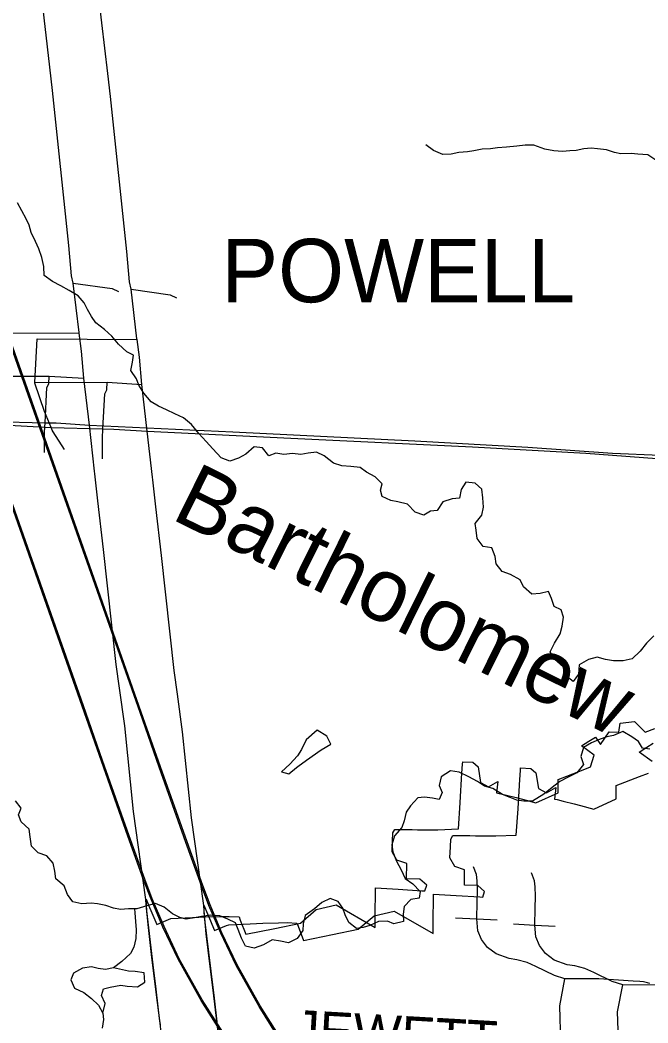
# Model space of a CAD drawing. Extents: x -38.2 to 41.9, y -4 to 24.9.
# Drawn here: x 7.082 to 8.019, y 16.76 to 18.257 of the extents above; entities that cross this region are included whole.
import ezdxf

# ---------------------------------------------------------------- set-up
doc = ezdxf.new("R2010")
doc.units = 0
for name, color, linetype in [('Default', 7, 'Continuous'), ('GM_X_City_Street', 7, 'Continuous'), ('GM_X_Corporation_Text', 7, 'Continuous'), ('GM_X_County_Road', 7, 'Continuous'), ('GM_X_Interchange_Ramps', 7, 'Continuous'), ('GM_X_Interstate_Location', 7, 'Continuous'), ('GM_X_Minor_Lake', 7, 'Continuous'), ('GM_X_Minor_River', 7, 'Continuous'), ('GM_X_Minor_River_Text', 7, 'Continuous'), ('GM_X_Rail_Line', 7, 'Continuous'), ('GM_X_Rail_Line_Text', 7, 'Continuous'), ('GM_X_State_Location', 7, 'Continuous'), ('GM_X_State_Route', 7, 'Continuous'), ('GM_X_Township_Road', 7, 'Continuous'), ('GM_X_Township_Road_Text', 7, 'Continuous')]:
    doc.layers.add(name, color=color, linetype=linetype)

msp = doc.modelspace()

# ---------------------------------------------------------------- linework, layer by layer
at = {"layer": 'Default'}
msp.add_lwpolyline([(7.2912, 16.7571), (7.2901, 16.7666), (7.2848, 16.8105), (7.2805, 16.8466), (7.2707, 16.9276), (7.2698, 16.9449), (7.2698, 16.945), (7.275, 16.9323), (7.2768, 16.9278), (7.2842, 16.9107), (7.2857, 16.9072), (7.3032, 16.9145), (7.3068, 16.9159), (7.3389, 16.9172), (7.3578, 16.9183), (7.3812, 16.9188), (7.3939, 16.9191), (7.4086, 16.9183), (7.4104, 16.9136), (7.4186, 16.8924), (7.4618, 16.9012), (7.5001, 16.9089), (7.5237, 16.9292), (7.5386, 16.9327), (7.5537, 16.9363), (7.6119, 16.9026), (7.612, 16.9141), (7.612, 16.9167), (7.6124, 16.9615), (7.6461, 16.9595), (7.6817, 16.9575), (7.6861, 16.9572), (7.6887, 16.9656), (7.6787, 16.9746), (7.6588, 16.975), (7.6589, 16.9979), (7.644, 17.0028), (7.637, 17.0154), (7.6378, 17.032), (7.6384, 17.0438), (7.6412, 17.0489), (7.6668, 17.049), (7.6752, 17.0485), (7.7056, 17.0485), (7.7361, 17.0497), (7.7387, 17.0887), (7.7387, 17.0892), (7.7414, 17.1328), (7.7423, 17.1462), (7.7425, 17.15), (7.7576, 17.1491), (7.7655, 17.1423), (7.7689, 17.1191), (7.7811, 17.1126), (7.7951, 17.1207), (7.7931, 17.1035), (7.7968, 17.1026), (7.8059, 17.1005), (7.8222, 17.0965), (7.8317, 17.0939), (7.8517, 17.0884), (7.8851, 17.1037), (7.885, 17.1236), (7.9198, 17.1371), (7.9333, 17.1423), (7.9387, 17.1597), (7.9197, 17.1736), (7.9309, 17.1807), (7.9405, 17.1869), (7.9482, 17.1757), (7.9612, 17.1945), (7.9758, 17.1942), (7.9776, 17.2075), (7.9987, 17.2102), (8.0059, 17.203), (8.0151, 17.194), (8.0295, 17.1998)], dxfattribs=at)
at = {"layer": 'GM_X_City_Street'}
msp.add_line((7.021, 17.7906), (7.1699, 17.7898), dxfattribs=at)
for points in [[(7.161, 17.8646), (7.2193, 17.8564), (7.2288, 17.8519)], [(7.0172, 17.7254), (7.125, 17.7257), (7.1769, 17.7225)], [(7.1183, 17.6425), (7.119, 17.6561), (7.1217, 17.7086), (7.1247, 17.7143), (7.125, 17.7257)], [(7.1182, 17.6115), (7.1182, 17.6415), (7.1183, 17.6425)]]:
    msp.add_lwpolyline(points, dxfattribs=at)
at = {"layer": 'GM_X_County_Road'}
for p, q in [((7.1262, 18.1868), (7.1021, 18.3947)), ((7.1928, 17.5839), (7.1852, 17.6526))]:
    msp.add_line(p, q, dxfattribs=at)
for points in [[(7.1698, 17.7908), (7.161, 17.8646), (7.1585, 17.8754), (7.1547, 17.9208), (7.1302, 18.1522), (7.1262, 18.1868)], [(7.1852, 17.6526), (7.1769, 17.7225), (7.1735, 17.763), (7.1699, 17.7898), (7.1698, 17.7908)], [(7.2302, 17.2599), (7.2254, 17.2953), (7.2063, 17.4669), (7.1978, 17.5395), (7.1933, 17.58), (7.1928, 17.5839)], [(7.27, 16.9364), (7.2693, 16.9444), (7.251, 17.0755), (7.2379, 17.2037), (7.2302, 17.2599)], [(8.0252, 17.1505), (8.0061, 17.1644), (8.0173, 17.1715), (8.027, 17.1777)], [(7.3766, 16.7574), (7.3713, 16.8013), (7.367, 16.8374), (7.3572, 16.9185), (7.3562, 16.9358), (7.3562, 16.9358), (7.3614, 16.9231), (7.3633, 16.9186), (7.3706, 16.9015), (7.3722, 16.898), (7.3897, 16.9053), (7.3933, 16.9067), (7.4254, 16.908), (7.4443, 16.9091), (7.4676, 16.9096), (7.4804, 16.9099), (7.4951, 16.9091), (7.4969, 16.9044), (7.505, 16.8832), (7.5482, 16.892), (7.5866, 16.8998), (7.6102, 16.92), (7.6251, 16.9236), (7.6402, 16.9271), (7.6984, 16.8934), (7.6985, 16.9049), (7.6985, 16.9075), (7.6989, 16.9523), (7.7326, 16.9503), (7.7682, 16.9483), (7.7726, 16.948), (7.7751, 16.9564), (7.7652, 16.9654), (7.7453, 16.9658), (7.7454, 16.9887), (7.7305, 16.9936), (7.7235, 17.0063), (7.7243, 17.0228), (7.7249, 17.0346), (7.7277, 17.0397), (7.7533, 17.0398), (7.7616, 17.0394), (7.7921, 17.0394), (7.8225, 17.0405), (7.8251, 17.0796), (7.8252, 17.0801), (7.8279, 17.1236), (7.8288, 17.137), (7.829, 17.1408), (7.8441, 17.1399), (7.8519, 17.1332), (7.8554, 17.1099), (7.8676, 17.1034), (7.8816, 17.1115), (7.8796, 17.0943), (7.8833, 17.0934), (7.8923, 17.0913), (7.9087, 17.0873), (7.9181, 17.0847), (7.9382, 17.0792), (7.9716, 17.0945), (7.9715, 17.1144), (8.0063, 17.1279), (8.0198, 17.1331)], [(7.2786, 16.8577), (7.2732, 16.9024), (7.27, 16.9364)], [(7.2918, 16.7497), (7.2911, 16.7556), (7.2843, 16.8099), (7.28, 16.846), (7.2786, 16.8577)]]:
    msp.add_lwpolyline(points, dxfattribs=at)
at = {"layer": 'GM_X_Interchange_Ramps'}
for points in [[(6.6529, 17.6722), (6.7596, 17.6658), (6.968, 17.6573), (7.0252, 17.6545), (7.0291, 17.6543), (7.1281, 17.6489), (7.2055, 17.6469), (7.2218, 17.6465), (7.2716, 17.6434)], [(7.2716, 17.6434), (7.4858, 17.6333), (7.7573, 17.62), (7.9264, 17.6105), (8.0524, 17.6013), (8.124, 17.5985), (8.2647, 17.5894)]]:
    msp.add_lwpolyline(points, dxfattribs=at)
at = {"layer": 'GM_X_Interstate_Location'}
msp.add_line((7.1074, 17.7814), (7.2563, 17.7806), dxfattribs=at)
for points in [[(7.2475, 17.8554), (7.3057, 17.8472), (7.3153, 17.8427)], [(7.1478, 17.6161), (7.1313, 17.6425), (7.1296, 17.6452), (7.1281, 17.6489), (7.1182, 17.6727), (7.1036, 17.715), (7.1036, 17.7163), (7.1074, 17.7814)], [(7.1036, 17.7163), (7.2115, 17.7165), (7.2634, 17.7134)], [(7.2048, 17.6333), (7.2055, 17.6469), (7.2082, 17.6994), (7.2112, 17.7051), (7.2115, 17.7165)], [(7.2047, 17.6023), (7.2047, 17.6323), (7.2048, 17.6333)]]:
    msp.add_lwpolyline(points, dxfattribs=at)
at = {"layer": 'GM_X_Minor_Lake'}
for points in [[(7.5254, 17.1972), (7.5087, 17.1828), (7.5019, 17.1683), (7.4959, 17.1589), (7.4842, 17.1464), (7.4721, 17.135), (7.4827, 17.1319), (7.4943, 17.1414)], [(7.4943, 17.1414), (7.4963, 17.1429), (7.5091, 17.1524), (7.5311, 17.1676), (7.5458, 17.1763), (7.5398, 17.1881), (7.5254, 17.1972)], [(7.2213, 16.8422), (7.2092, 16.8399), (7.1982, 16.8415), (7.1884, 16.8437), (7.1747, 16.8419), (7.1615, 16.8343), (7.1577, 16.8244), (7.163, 16.8119), (7.1767, 16.8054), (7.1884, 16.7963), (7.1986, 16.7868), (7.2054, 16.7747)], [(7.2054, 16.7747), (7.2085, 16.7891), (7.2031, 16.8012), (7.2065, 16.8111), (7.2164, 16.8134), (7.2319, 16.8164), (7.2417, 16.8149), (7.2569, 16.8137), (7.2682, 16.8209), (7.2671, 16.8346), (7.2535, 16.8369), (7.2436, 16.8373), (7.2213, 16.8422)]]:
    msp.add_lwpolyline(points, dxfattribs=at)
at = {"layer": 'GM_X_Minor_River'}
for points in [[(8.031, 18.0479), (8.0188, 18.0559), (8.0041, 18.057), (7.9939, 18.0578), (7.9787, 18.0574), (7.9689, 18.0597), (7.9572, 18.0635), (7.9439, 18.065), (7.9341, 18.0658), (7.9231, 18.065), (7.9121, 18.0627), (7.9023, 18.062), (7.8917, 18.0612), (7.8784, 18.062), (7.8652, 18.0643), (7.8489, 18.0707), (7.8357, 18.0704), (7.8232, 18.0692), (7.808, 18.0677), (7.7944, 18.0666), (7.7842, 18.0651), (7.7717, 18.0643), (7.7592, 18.0621), (7.7494, 18.0605), (7.7365, 18.0594), (7.7255, 18.0568), (7.7127, 18.0564), (7.6987, 18.0625), (7.6873, 18.0712)], [(7.2591, 17.7122), (7.2553, 17.7217), (7.247, 17.7342), (7.2496, 17.7467), (7.2511, 17.7569), (7.2413, 17.7619), (7.2288, 17.7733), (7.2189, 17.7854), (7.2079, 17.7953), (7.1947, 17.8052), (7.1883, 17.8146), (7.1826, 17.8249), (7.1773, 17.8351), (7.1682, 17.8454), (7.1549, 17.8537), (7.1428, 17.8606), (7.1299, 17.8667), (7.1175, 17.8761), (7.1171, 17.8894), (7.1144, 17.9027), (7.1099, 17.9156), (7.1046, 17.9266), (7.0985, 17.9399), (7.0951, 17.9509), (7.0909, 17.9604), (7.0845, 17.9725), (7.078, 17.9843)], [(8.0279, 17.338), (8.0169, 17.327), (8.0075, 17.3152), (7.9957, 17.3035), (7.9821, 17.3005), (7.9677, 17.3008), (7.9556, 17.3028), (7.9431, 17.3062), (7.9303, 17.3024), (7.9163, 17.2948), (7.9155, 17.2808), (7.9076, 17.2698), (7.8958, 17.2785), (7.8924, 17.2918), (7.8799, 17.3028), (7.8731, 17.3142), (7.8796, 17.3271), (7.8882, 17.3407), (7.8909, 17.3525), (7.8932, 17.3658), (7.8894, 17.3768), (7.8788, 17.3817), (7.875, 17.3935), (7.8704, 17.4041), (7.8583, 17.4011), (7.8455, 17.4003), (7.833, 17.411), (7.8284, 17.4216), (7.814, 17.4296), (7.8015, 17.4341), (7.7924, 17.4455), (7.7909, 17.4565), (7.786, 17.4694), (7.7728, 17.4713), (7.764, 17.4831), (7.7625, 17.4956), (7.761, 17.5059), (7.7708, 17.518), (7.7735, 17.5301), (7.7727, 17.5442), (7.7712, 17.5567), (7.761, 17.5658), (7.747, 17.5673), (7.7402, 17.5563), (7.7375, 17.5434), (7.7269, 17.5423), (7.7126, 17.5381), (7.7042, 17.5252), (7.6944, 17.5241), (7.6846, 17.5181), (7.6713, 17.5226), (7.6603, 17.5344), (7.6456, 17.5382), (7.635, 17.5401), (7.6225, 17.5458), (7.6198, 17.5553), (7.6225, 17.5651), (7.6119, 17.5754), (7.599, 17.5822), (7.5892, 17.5891), (7.5755, 17.591), (7.5619, 17.5917), (7.5498, 17.5959), (7.5358, 17.6069), (7.524, 17.6122), (7.5116, 17.6107), (7.501, 17.6085), (7.4885, 17.61), (7.4756, 17.6085), (7.4635, 17.6108), (7.4529, 17.6066), (7.4434, 17.6187), (7.4313, 17.6199), (7.4188, 17.6093), (7.4079, 17.6032), (7.3946, 17.5987), (7.3821, 17.6036), (7.3696, 17.6169), (7.3594, 17.6283), (7.3484, 17.64), (7.3374, 17.6533), (7.3257, 17.6632), (7.3128, 17.6693), (7.3003, 17.6754), (7.2886, 17.6807), (7.2773, 17.6871), (7.2663, 17.7004), (7.2591, 17.7122)], [(8.0219, 17.1688), (8.0109, 17.1703), (8.0049, 17.1802), (7.995, 17.1874), (7.9814, 17.195), (7.9678, 17.1893), (7.9576, 17.1874), (7.9477, 17.1836), (7.9349, 17.1783), (7.9228, 17.1711), (7.919, 17.1578), (7.9228, 17.1457), (7.9129, 17.1336), (7.9001, 17.1271), (7.8876, 17.1207), (7.8736, 17.1097), (7.8634, 17.1017), (7.8467, 17.0911), (7.8335, 17.0911), (7.8233, 17.0926)], [(7.8233, 17.0926), (7.8131, 17.0968), (7.8021, 17.101), (7.7877, 17.1101), (7.7752, 17.1135), (7.7646, 17.1204), (7.7517, 17.1272), (7.737, 17.1344), (7.7245, 17.1363), (7.7101, 17.1272), (7.7071, 17.1143), (7.712, 17.1041), (7.7071, 17.0938), (7.6973, 17.0954), (7.6855, 17.0973), (7.6757, 17.0961), (7.6647, 17.0844), (7.6579, 17.0745), (7.6553, 17.0616), (7.6515, 17.0518), (7.6409, 17.0393), (7.6367, 17.026), (7.6383, 17.0157), (7.6439, 17.0017), (7.6504, 16.9884), (7.6568, 16.9759), (7.6682, 16.9675), (7.6792, 16.9565), (7.6773, 16.9463), (7.6648, 16.9444), (7.6549, 16.9338), (7.6538, 16.9224), (7.6542, 16.9114), (7.6398, 16.908), (7.63, 16.9122), (7.6167, 16.9114), (7.6039, 16.9057), (7.5937, 16.9023), (7.5838, 16.9008), (7.5725, 16.9099), (7.5672, 16.9213), (7.5634, 16.9312), (7.5565, 16.9414), (7.5444, 16.9456), (7.5323, 16.9399), (7.521, 16.9304), (7.5074, 16.9202), (7.5043, 16.9081), (7.504, 16.8982), (7.4953, 16.8861), (7.4824, 16.8796), (7.4707, 16.8819), (7.4582, 16.8842), (7.4453, 16.8766), (7.4313, 16.8717), (7.4181, 16.8747), (7.4124, 16.8865), (7.4075, 16.8994), (7.4033, 16.9093), (7.3919, 16.915), (7.3798, 16.9199), (7.3662, 16.921), (7.3526, 16.9188), (7.342, 16.9169), (7.3299, 16.915), (7.32, 16.9173), (7.3094, 16.923), (7.2969, 16.9329), (7.2837, 16.9382), (7.2708, 16.9348), (7.2561, 16.9302), (7.2436, 16.9302), (7.2315, 16.9295), (7.2212, 16.9314), (7.2095, 16.9356), (7.1974, 16.9378), (7.1876, 16.939), (7.1739, 16.9379), (7.1607, 16.9409), (7.1527, 16.9519), (7.1474, 16.9648), (7.1349, 16.9754), (7.1338, 16.9864), (7.1311, 16.9986), (7.1217, 17.0096), (7.1088, 17.0138), (7.0986, 17.024), (7.0967, 17.0377), (7.0952, 17.0494), (7.0834, 17.0605), (7.0793, 17.0707), (7.0834, 17.0806), (7.0751, 17.0916)], [(7.2527, 16.9302), (7.253, 16.9245), (7.2538, 16.9116), (7.2549, 16.8991), (7.2546, 16.8862), (7.2516, 16.8733), (7.2466, 16.8638), (7.2338, 16.8517), (7.2213, 16.8422), (7.2092, 16.8399), (7.1982, 16.8415), (7.1884, 16.8437), (7.1747, 16.8419), (7.1615, 16.8343), (7.1577, 16.8244), (7.163, 16.8119), (7.1767, 16.8054), (7.1884, 16.7963), (7.1986, 16.7868), (7.2054, 16.7747), (7.2062, 16.7652), (7.2043, 16.7523)]]:
    msp.add_lwpolyline(points, dxfattribs=at)
at = {"layer": 'GM_X_Rail_Line'}
for points in [[(7.7706, 16.2837), (7.7436, 16.3196), (7.6853, 16.3873), (7.5326, 16.561), (7.4878, 16.6118), (7.4496, 16.6559), (7.4269, 16.6844), (7.4111, 16.7052), (7.3949, 16.7274), (7.3792, 16.7504), (7.352, 16.7937), (7.3177, 16.855), (7.2949, 16.9031), (7.2772, 16.9446), (7.2662, 16.9739), (7.2428, 17.0388), (7.2031, 17.151), (7.1745, 17.2327), (6.9922, 17.7506), (6.933, 17.9174), (6.8238, 18.2274), (6.6916, 18.6019)], [(7.7721, 16.2848), (7.7451, 16.3208), (7.6867, 16.3885), (7.534, 16.5622), (7.4893, 16.6131), (7.451, 16.6571), (7.4284, 16.6855), (7.4127, 16.7063), (7.3965, 16.7285), (7.3808, 16.7515), (7.3537, 16.7946), (7.3194, 16.8558), (7.2966, 16.9038), (7.279, 16.9453), (7.268, 16.9745), (7.2446, 17.0395), (7.2049, 17.1517), (7.1763, 17.2333), (6.994, 17.7513), (6.9348, 17.9181), (6.8256, 18.228), (6.6934, 18.6025)]]:
    msp.add_lwpolyline(points, dxfattribs=at)
at = {"layer": 'GM_X_Rail_Line_Text'}
for points in [[(7.8571, 16.2745), (7.8301, 16.3104), (7.7717, 16.3781), (7.6191, 16.5518), (7.5743, 16.6026), (7.5361, 16.6467), (7.5133, 16.6752), (7.4976, 16.696), (7.4814, 16.7182), (7.4657, 16.7413), (7.4385, 16.7845), (7.4042, 16.8458), (7.3813, 16.8939), (7.3637, 16.9355), (7.3527, 16.9647), (7.3293, 17.0296), (7.2895, 17.1418), (7.2609, 17.2235), (7.0786, 17.7415), (7.0195, 17.9082), (6.9103, 18.2182), (6.7781, 18.5927)], [(7.8586, 16.2756), (7.8316, 16.3116), (7.7732, 16.3793), (7.6205, 16.553), (7.5758, 16.6039), (7.5375, 16.6479), (7.5148, 16.6763), (7.4991, 16.6971), (7.483, 16.7193), (7.4673, 16.7423), (7.4401, 16.7854), (7.4059, 16.8466), (7.3831, 16.8947), (7.3654, 16.9362), (7.3545, 16.9654), (7.3311, 17.0303), (7.2913, 17.1425), (7.2627, 17.2241), (7.0804, 17.7421), (7.0213, 17.9089), (6.912, 18.2188), (6.7799, 18.5933)]]:
    msp.add_lwpolyline(points, dxfattribs=at)
at = {"layer": 'GM_X_State_Location'}
for points in [[(8.0324, 16.8165), (7.9816, 16.8168), (7.9658, 16.8219), (7.9384, 16.8351), (7.925, 16.8412), (7.9099, 16.8451), (7.8982, 16.847), (7.879, 16.8538), (7.866, 16.8635), (7.857, 16.8754), (7.8515, 16.8886), (7.8503, 16.9062), (7.8507, 16.9311), (7.8512, 16.9492), (7.8507, 16.9631), (7.8497, 16.9723), (7.8453, 16.9841)], [(7.8181, 16.9078), (7.8503, 16.9062), (7.8806, 16.9047)], [(7.9767, 16.669), (7.9757, 16.7214), (7.9738, 16.7767), (7.9816, 16.8168)]]:
    msp.add_lwpolyline(points, dxfattribs=at)
at = {"layer": 'GM_X_State_Route'}
for points in [[(6.5665, 17.6814), (6.6731, 17.675), (6.8815, 17.6665), (6.9387, 17.6637), (6.9426, 17.6635), (7.0416, 17.6581), (7.119, 17.6561), (7.1354, 17.6557), (7.1852, 17.6526)], [(7.1852, 17.6526), (7.3993, 17.6425), (7.6708, 17.6292), (7.8399, 17.6197), (7.9659, 17.6105), (8.0375, 17.6076), (8.1783, 17.5986)]]:
    msp.add_lwpolyline(points, dxfattribs=at)
at = {"layer": 'GM_X_Township_Road'}
for points in [[(8.0218, 16.8187), (8.0182, 16.8198), (8.0125, 16.8212), (8.0071, 16.822), (7.9971, 16.8226), (7.9459, 16.8257), (7.8951, 16.826), (7.8793, 16.8311), (7.8519, 16.8443), (7.8385, 16.8504), (7.8234, 16.8543), (7.8117, 16.8562), (7.7925, 16.863), (7.7795, 16.8726), (7.7706, 16.8845), (7.7651, 16.8977), (7.7638, 16.9154), (7.7642, 16.9403), (7.7648, 16.9584), (7.7642, 16.9722), (7.7632, 16.9815), (7.7588, 16.9933)], [(7.7316, 16.9169), (7.7638, 16.9154), (7.7941, 16.9139)], [(7.8902, 16.6781), (7.8892, 16.7306), (7.8873, 16.7858), (7.8951, 16.826)]]:
    msp.add_lwpolyline(points, dxfattribs=at)
at = {"layer": 'GM_X_Township_Road_Text'}
for p, q in [((7.2127, 18.1776), (7.1885, 18.3855)), ((7.2793, 17.5747), (7.2716, 17.6434))]:
    msp.add_line(p, q, dxfattribs=at)
for points in [[(7.2562, 17.7816), (7.2475, 17.8554), (7.245, 17.8662), (7.2412, 17.9117), (7.2167, 18.143), (7.2127, 18.1776)], [(7.2716, 17.6434), (7.2634, 17.7134), (7.26, 17.7538), (7.2563, 17.7806), (7.2562, 17.7816)], [(7.3167, 17.2507), (7.3119, 17.2862), (7.2928, 17.4577), (7.2843, 17.5303), (7.2797, 17.5708), (7.2793, 17.5747)], [(7.3565, 16.9272), (7.3558, 16.9352), (7.3375, 17.0663), (7.3244, 17.1945), (7.3167, 17.2507)], [(7.3651, 16.8485), (7.3597, 16.8932), (7.3565, 16.9272)], [(7.3783, 16.7405), (7.3775, 16.7464), (7.3708, 16.8007), (7.3665, 16.8368), (7.3651, 16.8485)]]:
    msp.add_lwpolyline(points, dxfattribs=at)

# ---------------------------------------------------------------- texts
at = {"layer": 'GM_X_Corporation_Text'}
msp.add_text('POWELL', height=0.0947, rotation=0, dxfattribs=at).set_placement((7.3824, 17.8359))
at = {"layer": 'GM_X_Minor_River_Text'}
msp.add_text('Bartholomew', height=0.0947, rotation=333.6958, dxfattribs=at).set_placement((7.3051, 17.5135))
at = {"layer": 'GM_X_Township_Road_Text'}
msp.add_text('JEWETT', height=0.05682, rotation=356.7399, dxfattribs=at).set_placement((7.489, 16.723))

doc.saveas('drawing.dxf')
